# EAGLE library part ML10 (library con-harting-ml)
HARTING
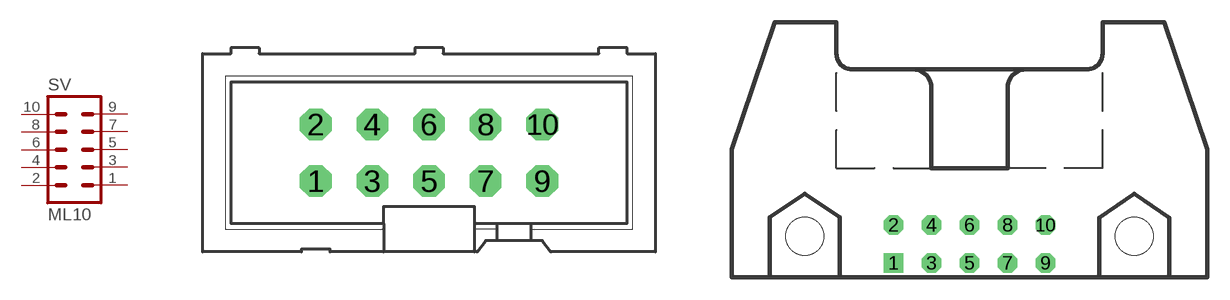
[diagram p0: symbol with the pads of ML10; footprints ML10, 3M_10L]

Designator prefix SV

## ML10  [ML10]
1  1  pas
2  2  pas
3  3  pas
4  4  pas
5  5  pas
6  6  pas
7  7  pas
8  8  pas
9  9  pas
10  10  pas

## ML10-3M  [3M_10L]
Pads as for ML10

## ML10L  [ML10L]
Pads as for ML10

## ML10-3ML  [3M_10L]
Pads as for ML10

## ML10-E  [ML14E]
Pads as for ML10

## Footprint ML10 (pad centres in mm)
HARTING
drill 0.914 octagon: 1 -5.08,-1.27; 2 -5.08,1.27; 3 -2.54,-1.27; 4 -2.54,1.27; 5 0,-1.27; 6 0,1.27; 7 2.54,-1.27; 8 2.54,1.27; 9 5.08,-1.27; 10 5.08,1.27

## Footprint 3M_10L (pad centres in mm)
HARTING
drill 0.813 square: 1 -5.08,-5.08
drill 0.813 octagon: 2 -5.08,-2.54; 3 -2.54,-5.08; 4 -2.54,-2.54; 5 0,-5.08; 6 0,-2.54; 7 2.54,-5.08; 8 2.54,-2.54; 9 5.08,-5.08; 10 5.08,-2.54
hole 2.54 at -10.998,-3.277
hole 2.54 at 10.998,-3.277

## Footprint ML10L (pad centres in mm)
HARTING
drill 0.914 octagon: 1 -5.08,-1.27; 2 -5.08,1.27; 3 -2.54,-1.27; 4 -2.54,1.27; 5 0,-1.27; 6 0,1.27; 7 2.54,-1.27; 8 2.54,1.27; 9 5.08,-1.27; 10 5.08,1.27

## Footprint ML14E (pad centres in mm)
drill 0.914 pad 1.829 square: 1 -7.62,-1.27
drill 0.914 pad 1.829 octagon: 2 -7.62,1.27; 3 -5.08,-1.27; 4 -5.08,1.27; 5 -2.54,-1.27; 6 -2.54,1.27; 7 0,-1.27; 8 0,1.27; 9 2.54,-1.27; 10 2.54,1.27; 11 5.08,-1.27; 12 5.08,1.27; 13 7.62,-1.27; 14 7.62,1.27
